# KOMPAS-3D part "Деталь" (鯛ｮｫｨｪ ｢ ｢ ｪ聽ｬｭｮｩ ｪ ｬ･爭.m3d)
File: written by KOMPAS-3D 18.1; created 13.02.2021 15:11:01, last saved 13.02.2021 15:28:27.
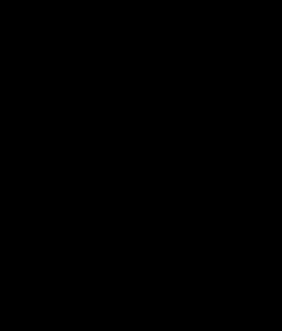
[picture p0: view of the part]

Document properties: Полное имя файла: C:\GoogleDrive\НИР\ИКИ\Компас\Столик в вакуумной камере.m3d

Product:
- Part/product: Деталь
    Масса: 0.169523

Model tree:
1. Эскиз:1
2. Элемент выдавливания:1
     Расстояние 1 = 4
3. Эскиз:2  (with: Элемент выдавливания:1)
4. Элемент выдавливания:2
     Расстояние 1 = 75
